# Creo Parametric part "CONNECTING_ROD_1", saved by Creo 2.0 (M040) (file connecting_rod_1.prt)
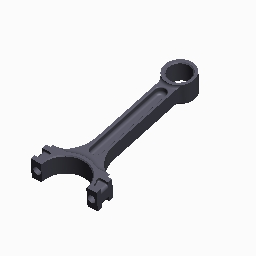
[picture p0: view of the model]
Units: millimeter Kilogram Sec (mmKs); MM, KILOGRAM, SECS

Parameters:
  MATERIAL = "ST37"

Created from: INLBS_PART_SOLID.PRT

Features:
  1. datum plane "RIGHT"
  2. datum plane "TOP"
  3. datum plane "FRONT"
  4. coordinate system
  5. datum plane "DTM4"
  6. datum axis "CRANKSHAFT_AXIS"
  7. datum axis "CON_BUSHING_AXIS"
  8. datum plane "DTM5"
  9. datum axis "A_13"
  10. mirror "Mirror 3"
  11. datum plane "DTM6"
  12. datum axis "A_13"
  13. datum point "Datum Point id 56", "PNT0"
  14. sketch "Sketch 1"
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
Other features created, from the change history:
  group "COPIED_GROUP"
  datum plane "DTM1" (2 times)
  datum plane "DTM2" (2 times)
  datum plane "DTM3" (2 times)
  coordinate system "CS0" (2 times)
  datum axis "CON_BUSHING_AXIS" (2 times)
  datum axis "CON_BOLT_AXIS_1" (2 times)
  datum axis "CON_BOLT_AXIS_2" (2 times)
  sketch "Sketch 2" (2 times)
  extrusion "Extrude 1" (2 times)
  extrusion "Extrude 2" (2 times)
  round "Round 1" (2 times)
  round "Round 2" (2 times)
  round "Round 3" (2 times)
  extruded cut "Extrude 3" (2 times)
  round "Round id 235" (2 times)
  hole "Hole 1" (2 times)
  hole "Hole 2" (2 times)
  chamfer "Chamfer 1" (2 times)
  chamfer "Chamfer 2" (2 times)
  extruded cut "Extrude 4" (2 times)
  mirror "Mirror 1" (2 times)
  extruded cut "Extrude 5" (2 times)
  round "Round 4" (2 times)
  round "Round 5" (2 times)
  round "Round 6" (2 times)
  round "Round 7" (2 times)
  group "LOCAL_GROUP" (2 times)
  extruded cut "Extrude 6" (2 times)
  round "Round 8" (2 times)
  round "Round 9" (2 times)
  round "Round 10" (2 times)
  mirror "Mirror 2" (2 times)
  group "LOCAL_GROUP_1" (2 times)
  extruded cut "Extrude 7" (2 times)
  round "Round 11" (2 times)
  round "Round 12" (2 times)
  round "Round 13" (2 times)
  datum axis "A_10" (2 times)
  datum axis "A_11" (2 times)
  datum axis "A_12"
  datum plane "DTM8"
